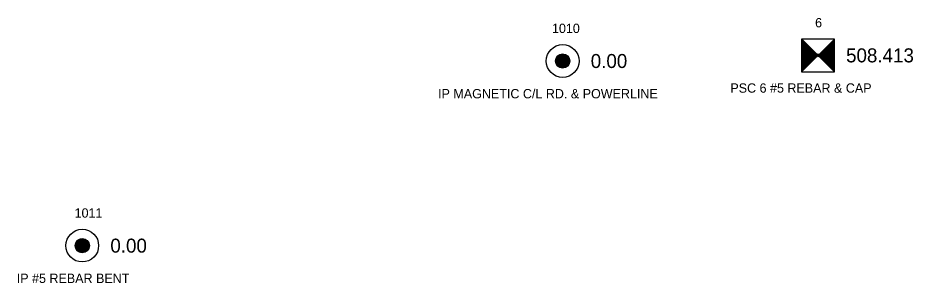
# Model space of a CAD drawing. Extents: x 1740701 to 1743138, y 748181 to 751839.
# Drawn here: x 1741037.2 to 1741132.9, y 749286.6 to 749315 of the extents above; entities that cross this region are included whole.
import ezdxf

# ---------------------------------------------------------------- set-up
doc = ezdxf.new("R2010")
doc.units = 0
for name, color, linetype in [('RD_EX_DV_Prop_txCode', 7, 'Continuous'), ('RD_EX_DV_PropPin', 7, 'Continuous'), ('RD_EX_TX_DV_Prop_ELEV', 7, 'Continuous'), ('RD_HC_Survey', 7, 'Continuous'), ('RD_HC_Survey_ELEV', 7, 'Continuous'), ('RD_HC_txCode', 7, 'Continuous'), ('RD_SMD_Locator', 7, 'Continuous')]:
    doc.layers.add(name, color=color, linetype=linetype)

msp = doc.modelspace()

# ---------------------------------------------------------------- linework, layer by layer
at = {"layer": 'RD_EX_DV_PropPin'}
for p, q in [((1741095.2, 749309.693), (1741095.2, 749311.134)), ((1741095.235, 749309.682), (1741095.235, 749311.145)), ((1741095.27, 749309.673), (1741095.27, 749311.154)), ((1741095.305, 749309.665), (1741095.305, 749311.161)), ((1741095.34, 749309.66), (1741095.34, 749311.167)), ((1741095.375, 749309.656), (1741095.375, 749311.171)), ((1741095.41, 749309.653), (1741095.41, 749311.174)), ((1741095.445, 749309.652), (1741095.445, 749311.174)), ((1741095.48, 749309.653), (1741095.48, 749311.174)), ((1741095.515, 749309.656), (1741095.515, 749311.171)), ((1741095.55, 749309.66), (1741095.55, 749311.167)), ((1741095.585, 749309.665), (1741095.585, 749311.161)), ((1741095.62, 749309.673), (1741095.62, 749311.154)), ((1741095.655, 749309.682), (1741095.655, 749311.145)), ((1741095.69, 749309.693), (1741095.69, 749311.134)), ((1741094.71, 749310.217), (1741094.71, 749310.61)), ((1741094.745, 749310.115), (1741094.745, 749310.711)), ((1741094.78, 749310.044), (1741094.78, 749310.783)), ((1741094.815, 749309.987), (1741094.815, 749310.84)), ((1741094.85, 749309.939), (1741094.85, 749310.888)), ((1741094.885, 749309.898), (1741094.885, 749310.928)), ((1741094.92, 749309.863), (1741094.92, 749310.964)), ((1741094.955, 749309.831), (1741094.955, 749310.996)), ((1741094.99, 749309.804), (1741094.99, 749311.023)), ((1741095.025, 749309.779), (1741095.025, 749311.048)), ((1741095.06, 749309.757), (1741095.06, 749311.07)), ((1741095.095, 749309.738), (1741095.095, 749311.089)), ((1741095.13, 749309.721), (1741095.13, 749311.106)), ((1741095.165, 749309.706), (1741095.165, 749311.121)), ((1741095.725, 749309.706), (1741095.725, 749311.121)), ((1741095.76, 749309.721), (1741095.76, 749311.106)), ((1741095.795, 749309.738), (1741095.795, 749311.089)), ((1741095.83, 749309.757), (1741095.83, 749311.07)), ((1741095.865, 749309.779), (1741095.865, 749311.048)), ((1741095.9, 749309.804), (1741095.9, 749311.023)), ((1741095.935, 749309.831), (1741095.935, 749310.996)), ((1741095.97, 749309.863), (1741095.97, 749310.964)), ((1741096.005, 749309.898), (1741096.005, 749310.928)), ((1741096.04, 749309.939), (1741096.04, 749310.888)), ((1741096.075, 749309.987), (1741096.075, 749310.84)), ((1741096.11, 749310.044), (1741096.11, 749310.783)), ((1741096.145, 749310.115), (1741096.145, 749310.711)), ((1741096.18, 749310.217), (1741096.18, 749310.61)), ((1741043.487, 749290.214), (1741043.487, 749291.067)), ((1741043.522, 749290.166), (1741043.522, 749291.115)), ((1741043.557, 749290.125), (1741043.557, 749291.156)), ((1741043.592, 749290.09), (1741043.592, 749291.191)), ((1741043.627, 749290.058), (1741043.627, 749291.223)), ((1741043.662, 749290.031), (1741043.662, 749291.25)), ((1741043.697, 749290.006), (1741043.697, 749291.275)), ((1741043.732, 749289.984), (1741043.732, 749291.297)), ((1741043.767, 749289.965), (1741043.767, 749291.316)), ((1741043.802, 749289.948), (1741043.802, 749291.333)), ((1741043.837, 749289.933), (1741043.837, 749291.348)), ((1741043.872, 749289.92), (1741043.872, 749291.361)), ((1741043.907, 749289.909), (1741043.907, 749291.372)), ((1741043.942, 749289.9), (1741043.942, 749291.381)), ((1741043.977, 749289.892), (1741043.977, 749291.389)), ((1741044.012, 749289.887), (1741044.012, 749291.394)), ((1741044.047, 749289.883), (1741044.047, 749291.398)), ((1741044.082, 749289.88), (1741044.082, 749291.401)), ((1741044.117, 749289.879), (1741044.117, 749291.402)), ((1741044.152, 749289.88), (1741044.152, 749291.401)), ((1741044.187, 749289.883), (1741044.187, 749291.398)), ((1741044.222, 749289.887), (1741044.222, 749291.394)), ((1741044.257, 749289.892), (1741044.257, 749291.389)), ((1741044.292, 749289.9), (1741044.292, 749291.381)), ((1741044.327, 749289.909), (1741044.327, 749291.372)), ((1741044.362, 749289.92), (1741044.362, 749291.361)), ((1741044.397, 749289.933), (1741044.397, 749291.348)), ((1741044.432, 749289.948), (1741044.432, 749291.333)), ((1741044.467, 749289.965), (1741044.467, 749291.316)), ((1741044.502, 749289.984), (1741044.502, 749291.297)), ((1741044.537, 749290.006), (1741044.537, 749291.275)), ((1741044.572, 749290.031), (1741044.572, 749291.25)), ((1741044.607, 749290.058), (1741044.607, 749291.223)), ((1741044.642, 749290.09), (1741044.642, 749291.191)), ((1741044.677, 749290.125), (1741044.677, 749291.156)), ((1741044.712, 749290.166), (1741044.712, 749291.115)), ((1741044.747, 749290.214), (1741044.747, 749291.067)), ((1741043.382, 749290.444), (1741043.382, 749290.837)), ((1741043.417, 749290.343), (1741043.417, 749290.938)), ((1741043.452, 749290.271), (1741043.452, 749291.01)), ((1741044.782, 749290.271), (1741044.782, 749291.01)), ((1741044.817, 749290.343), (1741044.817, 749290.938)), ((1741044.852, 749290.444), (1741044.852, 749290.837))]:
    msp.add_line(p, q, dxfattribs=at)
for centre, radius in [((1741095.445, 749310.413), 1.75), ((1741095.445, 749310.413), 0.761), ((1741044.117, 749290.64), 1.75), ((1741044.117, 749290.64), 0.761)]:
    msp.add_circle(centre, radius, dxfattribs=at)
at = {"layer": 'RD_HC_Survey'}
for p, q in [((1741120.976, 749312.768), (1741124.476, 749309.268)), ((1741124.476, 749312.768), (1741120.976, 749309.268)), ((1741121.001, 749312.743), (1741121.001, 749309.293)), ((1741121.026, 749312.719), (1741121.026, 749309.318)), ((1741121.051, 749312.694), (1741121.051, 749309.342)), ((1741121.075, 749312.669), (1741121.075, 749309.367)), ((1741121.1, 749312.644), (1741121.1, 749309.392)), ((1741121.125, 749312.62), (1741121.125, 749309.417)), ((1741121.15, 749312.595), (1741121.15, 749309.441)), ((1741121.174, 749312.57), (1741121.174, 749309.466)), ((1741121.199, 749312.545), (1741121.199, 749309.491)), ((1741121.224, 749312.521), (1741121.224, 749309.516)), ((1741121.249, 749312.496), (1741121.249, 749309.54)), ((1741121.273, 749312.471), (1741121.273, 749309.565)), ((1741121.298, 749312.446), (1741121.298, 749309.59)), ((1741121.323, 749312.422), (1741121.323, 749309.615)), ((1741121.348, 749312.397), (1741121.348, 749309.639)), ((1741121.372, 749312.372), (1741121.372, 749309.664)), ((1741121.397, 749312.347), (1741121.397, 749309.689)), ((1741121.422, 749312.323), (1741121.422, 749309.714)), ((1741121.447, 749312.298), (1741121.447, 749309.738)), ((1741121.471, 749312.273), (1741121.471, 749309.763)), ((1741121.496, 749312.248), (1741121.496, 749309.788)), ((1741121.521, 749312.224), (1741121.521, 749309.813)), ((1741121.546, 749312.199), (1741121.546, 749309.837)), ((1741121.57, 749312.174), (1741121.57, 749309.862)), ((1741121.595, 749312.149), (1741121.595, 749309.887)), ((1741121.62, 749312.125), (1741121.62, 749309.912)), ((1741121.645, 749312.1), (1741121.645, 749309.936)), ((1741123.808, 749312.1), (1741123.808, 749309.936)), ((1741123.833, 749312.125), (1741123.833, 749309.912)), ((1741123.858, 749312.149), (1741123.858, 749309.887)), ((1741123.882, 749312.174), (1741123.882, 749309.862)), ((1741123.907, 749312.199), (1741123.907, 749309.837)), ((1741123.932, 749312.224), (1741123.932, 749309.813)), ((1741123.957, 749312.248), (1741123.957, 749309.788)), ((1741123.981, 749312.273), (1741123.981, 749309.763)), ((1741124.006, 749312.298), (1741124.006, 749309.738)), ((1741124.031, 749312.323), (1741124.031, 749309.714)), ((1741124.056, 749312.347), (1741124.056, 749309.689)), ((1741124.08, 749312.372), (1741124.08, 749309.664)), ((1741124.105, 749312.397), (1741124.105, 749309.639)), ((1741124.13, 749312.422), (1741124.13, 749309.615)), ((1741124.155, 749312.446), (1741124.155, 749309.59)), ((1741124.179, 749312.471), (1741124.179, 749309.565)), ((1741124.204, 749312.496), (1741124.204, 749309.54)), ((1741124.229, 749312.521), (1741124.229, 749309.516)), ((1741124.254, 749312.545), (1741124.254, 749309.491)), ((1741124.278, 749312.57), (1741124.278, 749309.466)), ((1741124.303, 749312.595), (1741124.303, 749309.441)), ((1741124.328, 749312.62), (1741124.328, 749309.417)), ((1741124.353, 749312.644), (1741124.353, 749309.392)), ((1741124.377, 749312.669), (1741124.377, 749309.367)), ((1741124.402, 749312.694), (1741124.402, 749309.342)), ((1741124.427, 749312.719), (1741124.427, 749309.318)), ((1741124.452, 749312.743), (1741124.452, 749309.293)), ((1741121.669, 749312.075), (1741121.669, 749309.961)), ((1741121.694, 749312.05), (1741121.694, 749309.986)), ((1741121.719, 749312.026), (1741121.719, 749310.011)), ((1741121.744, 749312.001), (1741121.744, 749310.035)), ((1741121.768, 749311.976), (1741121.768, 749310.06)), ((1741121.793, 749311.951), (1741121.793, 749310.085)), ((1741121.818, 749311.927), (1741121.818, 749310.11)), ((1741121.843, 749311.902), (1741121.843, 749310.134)), ((1741121.867, 749311.877), (1741121.867, 749310.159)), ((1741121.892, 749311.852), (1741121.892, 749310.184)), ((1741121.917, 749311.828), (1741121.917, 749310.209)), ((1741121.942, 749311.803), (1741121.942, 749310.233)), ((1741121.966, 749311.778), (1741121.966, 749310.258)), ((1741121.991, 749311.753), (1741121.991, 749310.283)), ((1741122.016, 749311.729), (1741122.016, 749310.308)), ((1741122.04, 749311.704), (1741122.04, 749310.332)), ((1741122.065, 749311.679), (1741122.065, 749310.357)), ((1741122.09, 749311.655), (1741122.09, 749310.382)), ((1741122.115, 749311.63), (1741122.115, 749310.407)), ((1741122.139, 749311.605), (1741122.139, 749310.431)), ((1741122.164, 749311.58), (1741122.164, 749310.456)), ((1741122.189, 749311.556), (1741122.189, 749310.481)), ((1741122.214, 749311.531), (1741122.214, 749310.506)), ((1741122.238, 749311.506), (1741122.238, 749310.53)), ((1741122.263, 749311.481), (1741122.263, 749310.555)), ((1741122.288, 749311.457), (1741122.288, 749310.58)), ((1741122.313, 749311.432), (1741122.313, 749310.605)), ((1741122.337, 749311.407), (1741122.337, 749310.629)), ((1741122.362, 749311.382), (1741122.362, 749310.654)), ((1741122.387, 749311.358), (1741122.387, 749310.679)), ((1741122.412, 749311.333), (1741122.412, 749310.704)), ((1741122.436, 749311.308), (1741122.436, 749310.728)), ((1741122.461, 749311.283), (1741122.461, 749310.753)), ((1741122.486, 749311.259), (1741122.486, 749310.778)), ((1741122.511, 749311.234), (1741122.511, 749310.803)), ((1741122.535, 749311.209), (1741122.535, 749310.827)), ((1741122.56, 749311.184), (1741122.56, 749310.852)), ((1741122.585, 749311.16), (1741122.585, 749310.877)), ((1741122.61, 749311.135), (1741122.61, 749310.902)), ((1741122.843, 749311.135), (1741122.843, 749310.902)), ((1741122.868, 749311.16), (1741122.868, 749310.877)), ((1741122.892, 749311.184), (1741122.892, 749310.852)), ((1741122.917, 749311.209), (1741122.917, 749310.827)), ((1741122.942, 749311.234), (1741122.942, 749310.803)), ((1741122.967, 749311.259), (1741122.967, 749310.778)), ((1741122.991, 749311.283), (1741122.991, 749310.753)), ((1741123.016, 749311.308), (1741123.016, 749310.728)), ((1741123.041, 749311.333), (1741123.041, 749310.704)), ((1741123.066, 749311.358), (1741123.066, 749310.679)), ((1741123.09, 749311.382), (1741123.09, 749310.654)), ((1741123.115, 749311.407), (1741123.115, 749310.629)), ((1741123.14, 749311.432), (1741123.14, 749310.605)), ((1741123.165, 749311.457), (1741123.165, 749310.58)), ((1741123.189, 749311.481), (1741123.189, 749310.555)), ((1741123.214, 749311.506), (1741123.214, 749310.53)), ((1741123.239, 749311.531), (1741123.239, 749310.506)), ((1741123.264, 749311.556), (1741123.264, 749310.481)), ((1741123.288, 749311.58), (1741123.288, 749310.456)), ((1741123.313, 749311.605), (1741123.313, 749310.431)), ((1741123.338, 749311.63), (1741123.338, 749310.407)), ((1741123.363, 749311.655), (1741123.363, 749310.382)), ((1741123.387, 749311.679), (1741123.387, 749310.357)), ((1741123.412, 749311.704), (1741123.412, 749310.332)), ((1741123.437, 749311.729), (1741123.437, 749310.308)), ((1741123.462, 749311.753), (1741123.462, 749310.283)), ((1741123.486, 749311.778), (1741123.486, 749310.258)), ((1741123.511, 749311.803), (1741123.511, 749310.233)), ((1741123.536, 749311.828), (1741123.536, 749310.209)), ((1741123.561, 749311.852), (1741123.561, 749310.184)), ((1741123.585, 749311.877), (1741123.585, 749310.159)), ((1741123.61, 749311.902), (1741123.61, 749310.134)), ((1741123.635, 749311.927), (1741123.635, 749310.11)), ((1741123.66, 749311.951), (1741123.66, 749310.085)), ((1741123.684, 749311.976), (1741123.684, 749310.06)), ((1741123.709, 749312.001), (1741123.709, 749310.035)), ((1741123.734, 749312.026), (1741123.734, 749310.011)), ((1741123.759, 749312.05), (1741123.759, 749309.986)), ((1741123.783, 749312.075), (1741123.783, 749309.961)), ((1741122.634, 749311.11), (1741122.634, 749310.926)), ((1741122.659, 749311.085), (1741122.659, 749310.951)), ((1741122.684, 749311.061), (1741122.684, 749310.976)), ((1741122.709, 749311.036), (1741122.709, 749311.001)), ((1741122.744, 749311.036), (1741122.744, 749311.001)), ((1741122.769, 749311.061), (1741122.769, 749310.976)), ((1741122.793, 749311.085), (1741122.793, 749310.951)), ((1741122.818, 749311.11), (1741122.818, 749310.926))]:
    msp.add_line(p, q, dxfattribs=at)
msp.add_lwpolyline([(1741124.476, 749312.768), (1741120.976, 749312.768), (1741120.976, 749309.268), (1741124.476, 749309.268)], close=True, dxfattribs=at)
at = {"layer": 'RD_SMD_Locator'}
for centre in [(1741122.726, 749311.018), (1741095.445, 749310.413), (1741044.117, 749290.64)]:
    msp.add_circle(centre, 0.15, dxfattribs=at)

# ---------------------------------------------------------------- texts
at = {"layer": 'RD_EX_DV_Prop_txCode'}
for s, p in [('1010', (1741094.303, 749313.413)), ('IP MAGNETIC C/L RD. & POWERLINE', (1741082.134, 749306.413)), ('1011', (1741043.298, 749293.641)), ('IP #5 REBAR BENT', (1741037.117, 749286.641))]:
    msp.add_text(s, height=1, dxfattribs=at).set_placement(p)
at = {"layer": 'RD_EX_TX_DV_Prop_ELEV'}
for p in [(1741098.445, 749309.663), (1741047.117, 749289.891)]:
    msp.add_text('0.00', height=1.5, dxfattribs=at).set_placement(p)
at = {"layer": 'RD_HC_Survey_ELEV'}
msp.add_text('508.413', height=1.5, dxfattribs=at).set_placement((1741125.726, 749310.268))
at = {"layer": 'RD_HC_txCode'}
for s, p in [('6', (1741122.419, 749314.018)), ('PSC 6 #5 REBAR & CAP', (1741113.364, 749307.018))]:
    msp.add_text(s, height=1, dxfattribs=at).set_placement(p)

doc.saveas('drawing.dxf')
